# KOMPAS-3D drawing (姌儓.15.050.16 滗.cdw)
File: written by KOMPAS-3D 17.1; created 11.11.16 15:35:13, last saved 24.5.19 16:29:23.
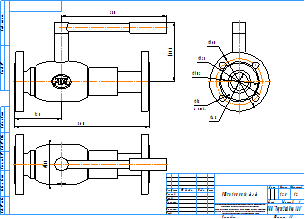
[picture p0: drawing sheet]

Sheet 1: A3, landscape

Title block, sheet 1: name: КШГИ.15.050.16 ф/ф; mass: 12,5; sheets: 1; organisation: ООО "Торговый дом АДЛ"; sheet format: A3; stored path: C:\Users\kka\KOMPAS_Work\КШП.ГИ\Ду50\КШГИ.15.50.16 ГЧ _ Кран шаровой газовый изолирующий  БИВАЛ Ду50 Ру16  полнопроходной фланцевый Габаритный чертеж.cdw

Views: Вид 1, Проекционный вид 2, Проекционный вид 3
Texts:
  Klimkovich
  ADL
  Рама для чертежей
  Лит-Масса-Масштаб
  Материал-Предприятие
  Масштаб
  Изм.
  Лист
  № докум.
  Подп.
  Дата
  Лит.
  Разраб.
  Пров.
  Т.контр.
  Листов
  Внимание! Данный продукт является объектом авторского права ООО «Торговый Дом АДЛ».
  Запрещается изменение, копирование, распространение
  (в том числе путем копирования на другие сайты и ресурсы в Интернете)
  или любое иное использование информации и объектов без предварительного
  согласия правообладателя (ООО «Торговый Дом АДЛ»).
  Н.контр.
  Утв.
  Изменение
  Номер документа
  Подпись
  Обозначение документа
  Наименование изделия
  Масса изделия по ГОСТ 2.109-73
  Порядковый номер листа
  Общее количество листов в документе
  Характер работы, выполненной лицом, подписавшим документ
  Наименование или индекс предприятия, выпускающего документ
  Инв. № подл.
  Подп. и дата
  Взам. инв. №
  Инв. № дубл.
  Инвентарный номер подлинника по ГОСТ 2.501-68
  Подпись принявшего подлинник в отдел технической документации
  Инвентарный номер подлинника, взамен которого выпущен данный подлинник
  Инвентарный номер дубликата по ГОСТ 2.502-68
  Подпись принявшего дубликат в отдел технической документации
  Справ. №
  Перв. примен.
  Обозначение документа, взамен или на основании которого выпущен данный документ
  Обозначение документа, в котором впервые записан данный документ
  Подпись лица, копировавшего чертеж
  Обозначение формата листа
  !Рама для чертежа
Dimensions and other numbers on the sheet: 360; 125; 280; 159,3; 160; 102; 48; 18; 4 отв.; 108; 1:2; 1; 12,5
